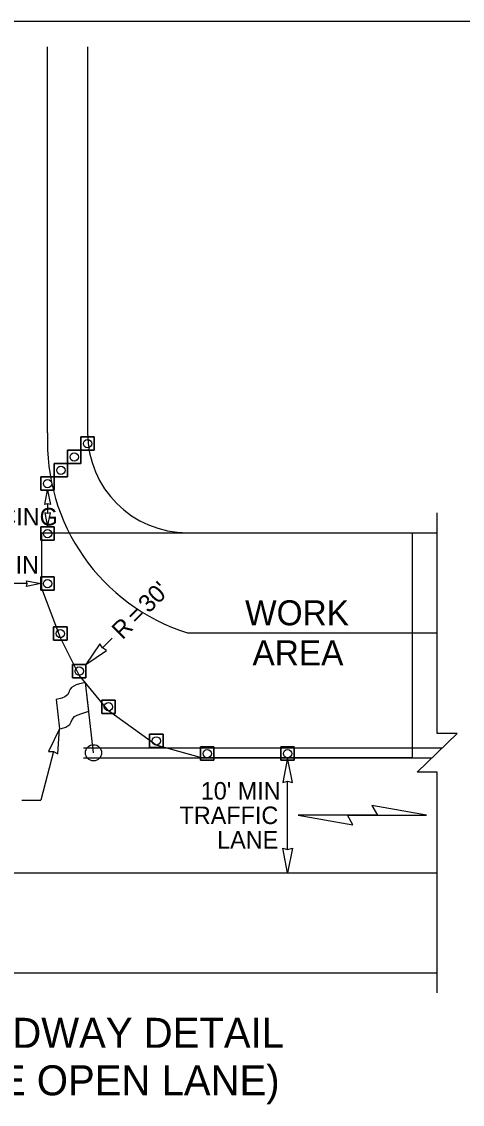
# Model space of a CAD drawing. Extents: x 99999.1 to 100095.7, y 99995 to 100010.7.
# Drawn here: x 100028.611 to 100030.375, y 100001.65 to 100005.98 of the extents above; entities that cross this region are included whole.
import ezdxf

# ---------------------------------------------------------------- set-up
doc = ezdxf.new("R2010")
doc.units = 0
for name, color, linetype in [('RD_ED_ShoulderPavedEdge', 7, 'Continuous'), ('RD_MK_LineDblYellowCenter', 7, 'Continuous'), ('RD_MK_LineEdgeWhite', 7, 'Continuous'), ('SH_DE_DetailHeading2Text', 7, 'Continuous'), ('TR_WZ_FlaggingStation', 7, 'Continuous'), ('TR_WZ_TrafficCone', 7, 'Continuous'), ('TR_WZ_WorkAreaLabel', 7, 'Continuous'), ('TR_WZ_WorkZoneDetails', 7, 'Continuous'), ('TR_WZ_WorkZoneTextCurrent', 7, 'Continuous')]:
    doc.layers.add(name, color=color, linetype=linetype)

msp = doc.modelspace()

# ---------------------------------------------------------------- linework, layer by layer
at = {"layer": 'RD_ED_ShoulderPavedEdge'}
for p, q in [((100029.275, 100003.9359), (100030.275, 100003.9359)), ((100025.475, 100002.1759), (100030.275, 100002.1759))]:
    msp.add_line(p, q, dxfattribs=at)
msp.add_lwpolyline([(100028.875, 100005.8804), (100028.875, 100004.3359)], dxfattribs=at)
msp.add_arc((100029.275, 100004.3359), 0.4, 180, 270, dxfattribs=at)
at = {"layer": 'RD_MK_LineDblYellowCenter'}
for p, q in [((100028.8588, 100003.0759), (100030.2957, 100003.0759)), ((100028.8588, 100003.0359), (100030.2543, 100003.0359))]:
    msp.add_line(p, q, dxfattribs=at)
at = {"layer": 'RD_MK_LineEdgeWhite'}
for p, q in [((100028.715, 100004.3359), (100028.715, 100005.8804)), ((100029.275, 100003.5359), (100030.275, 100003.5359)), ((100025.475, 100002.5759), (100030.275, 100002.5759))]:
    msp.add_line(p, q, dxfattribs=at)
msp.add_arc((100029.5142, 100004.2993), 0.8, 177.3788, 252.6052, dxfattribs=at)
at = {"layer": 'TR_WZ_FlaggingStation'}
for p, q in [((100028.8797, 100003.2228), (100028.8667, 100003.3371)), ((100028.8988, 100003.0559), (100028.8667, 100003.3368)), ((100028.7487, 100003.2693), (100028.762, 100003.1521)), ((100028.8797, 100003.2228), (100028.8797, 100003.2228))]:
    msp.add_line(p, q, dxfattribs=at)
for points in [[(100028.8667, 100003.3371), (100028.8609, 100003.3359), (100028.8431, 100003.3324), (100028.8293, 100003.3283), (100028.8196, 100003.3222), (100028.8111, 100003.3175), (100028.8054, 100003.3106), (100028.8012, 100003.3028), (100028.8006, 100003.2966), (100028.7953, 100003.2874), (100028.7845, 100003.2799), (100028.7721, 100003.2747), (100028.7487, 100003.2693)], [(100028.762, 100003.1521), (100028.7702, 100003.1536), (100028.7879, 100003.1582), (100028.8035, 100003.1687), (100028.81, 100003.1793), (100028.814, 100003.1896), (100028.823, 100003.2005), (100028.834, 100003.2067), (100028.8514, 100003.2138), (100028.8797, 100003.2228)]]:
    msp.add_lwpolyline(points, dxfattribs=at)
msp.add_circle((100028.8988, 100003.0559), 0.0325, dxfattribs=at)
at = {"layer": 'TR_WZ_TrafficCone'}
for points in [[(100028.8483, 100004.3192), (100028.9016, 100004.3192), (100028.9016, 100004.2659), (100028.8483, 100004.2659), (100028.8483, 100004.3192)], [(100028.8483, 100004.2659), (100028.9016, 100004.2659), (100028.9016, 100004.3192), (100028.8483, 100004.3192), (100028.8483, 100004.2659)], [(100028.795, 100004.2659), (100028.8483, 100004.2659), (100028.8483, 100004.2126), (100028.795, 100004.2126), (100028.795, 100004.2659)], [(100028.795, 100004.2126), (100028.8483, 100004.2126), (100028.8483, 100004.2659), (100028.795, 100004.2659), (100028.795, 100004.2126)], [(100028.7416, 100004.2126), (100028.795, 100004.2126), (100028.795, 100004.1592), (100028.7416, 100004.1592), (100028.7416, 100004.2126)], [(100028.7416, 100004.1592), (100028.795, 100004.1592), (100028.795, 100004.2126), (100028.7416, 100004.2126), (100028.7416, 100004.1592)], [(100028.7416, 100004.1592), (100028.6883, 100004.1592), (100028.6883, 100004.1059), (100028.7416, 100004.1059), (100028.7416, 100004.1592)], [(100028.7416, 100004.1059), (100028.6883, 100004.1059), (100028.6883, 100004.1592), (100028.7416, 100004.1592), (100028.7416, 100004.1059)], [(100028.7416, 100003.9592), (100028.6883, 100003.9592), (100028.6883, 100003.9059), (100028.7416, 100003.9059), (100028.7416, 100003.9592)], [(100028.7416, 100003.9059), (100028.6883, 100003.9059), (100028.6883, 100003.9592), (100028.7416, 100003.9592), (100028.7416, 100003.9059)], [(100028.7416, 100003.7592), (100028.6883, 100003.7592), (100028.6883, 100003.7059), (100028.7416, 100003.7059), (100028.7416, 100003.7592)], [(100028.7416, 100003.7059), (100028.6883, 100003.7059), (100028.6883, 100003.7592), (100028.7416, 100003.7592), (100028.7416, 100003.7059)], [(100028.7927, 100003.5592), (100028.7393, 100003.5592), (100028.7393, 100003.5059), (100028.7927, 100003.5059), (100028.7927, 100003.5592)], [(100028.7927, 100003.5059), (100028.7393, 100003.5059), (100028.7393, 100003.5592), (100028.7927, 100003.5592), (100028.7927, 100003.5059)], [(100028.8683, 100003.4093), (100028.815, 100003.4093), (100028.815, 100003.3559), (100028.8683, 100003.3559), (100028.8683, 100003.4093)], [(100028.8683, 100003.3559), (100028.815, 100003.3559), (100028.815, 100003.4093), (100028.8683, 100003.4093), (100028.8683, 100003.3559)], [(100028.9853, 100003.267), (100028.9319, 100003.267), (100028.9319, 100003.2136), (100028.9853, 100003.2136), (100028.9853, 100003.267)], [(100028.9853, 100003.2136), (100028.9319, 100003.2136), (100028.9319, 100003.267), (100028.9853, 100003.267), (100028.9853, 100003.2136)], [(100029.177, 100003.1302), (100029.1236, 100003.1302), (100029.1236, 100003.0768), (100029.177, 100003.0768), (100029.177, 100003.1302)], [(100029.177, 100003.0768), (100029.1236, 100003.0768), (100029.1236, 100003.1302), (100029.177, 100003.1302), (100029.177, 100003.0768)], [(100029.381, 100003.0792), (100029.3276, 100003.0792), (100029.3276, 100003.0259), (100029.381, 100003.0259), (100029.381, 100003.0792)], [(100029.381, 100003.0259), (100029.3276, 100003.0259), (100029.3276, 100003.0792), (100029.381, 100003.0792), (100029.381, 100003.0259)], [(100029.649, 100003.0792), (100029.7024, 100003.0792), (100029.7024, 100003.0259), (100029.649, 100003.0259), (100029.649, 100003.0792)], [(100029.649, 100003.0259), (100029.7024, 100003.0259), (100029.7024, 100003.0792), (100029.649, 100003.0792), (100029.649, 100003.0259)]]:
    msp.add_lwpolyline(points, dxfattribs=at)
for centre in [(100028.875, 100004.2926), (100028.8216, 100004.2392), (100028.7683, 100004.1859), (100028.715, 100004.1326), (100028.715, 100003.9326), (100028.715, 100003.7326), (100028.766, 100003.5326), (100028.8417, 100003.3826), (100028.9586, 100003.2403), (100029.1503, 100003.1035), (100029.3543, 100003.0526), (100029.6757, 100003.0526)]:
    msp.add_circle(centre, 0.0167, dxfattribs=at)
at = {"layer": 'TR_WZ_WorkZoneDetails'}
for p, q in [((100030.5, 100005.9804), (100025.25, 100005.9804)), ((100028.715, 100004.0514), (100028.715, 100004.0137)), ((100028.6338, 100003.7326), (100028.3962, 100003.7326)), ((100028.9346, 100003.4755), (100028.973, 100003.514)), ((100028.7385, 100003.0614), (100028.688, 100002.8668)), ((100029.6756, 100002.6696), (100029.6756, 100002.9422)), ((100028.6118, 100002.8668), (100028.688, 100002.8668)), ((100030.0356, 100002.8059), (100029.7945, 100002.8059)), ((100029.9151, 100002.8059), (100030.1562, 100002.8059))]:
    msp.add_line(p, q, dxfattribs=at)
for points in [[(100028.715, 100004.1059), (100028.7262, 100004.0487), (100028.715, 100004.0514), (100028.7037, 100004.0487)], [(100028.715, 100003.9592), (100028.7262, 100004.0164), (100028.715, 100004.0137), (100028.7038, 100004.0164)], [(100030.175, 100003.9359), (100030.175, 100003.0359), (100029.699, 100003.0359), (100029.6523, 100003.0359), (100029.6523, 100003.0359), (100029.6523, 100003.0359), (100029.331, 100003.0359), (100029.331, 100003.0359), (100029.331, 100003.0359), (100029.1503, 100003.0868), (100028.9586, 100003.2236), (100028.8417, 100003.3659), (100028.766, 100003.5159), (100028.6917, 100003.7126), (100028.6917, 100003.9359)], [(100028.6883, 100003.7326), (100028.6311, 100003.7214), (100028.6338, 100003.7326), (100028.6311, 100003.7438)], [(100028.8683, 100003.4093), (100028.9514, 100003.4652), (100028.9346, 100003.4756), (100028.9242, 100003.4924)], [(100028.762, 100003.1521), (100028.7187, 100003.0618), (100028.7385, 100003.0614), (100028.7561, 100003.0522)], [(100029.6757, 100003.0359), (100029.6564, 100002.9376), (100029.6757, 100002.9422), (100029.695, 100002.9376)], [(100030.2321, 100002.8059), (100030.0133, 100002.8445), (100030.0356, 100002.8059)], [(100029.7185, 100002.8059), (100029.9373, 100002.7673), (100029.9151, 100002.8059)], [(100029.6756, 100002.5759), (100029.6564, 100002.6742), (100029.6756, 100002.6696), (100029.6949, 100002.6742)]]:
    msp.add_lwpolyline(points, close=True, dxfattribs=at)
msp.add_lwpolyline([(100030.275, 100002.0959), (100030.275, 100002.9785), (100030.195, 100002.9785), (100030.355, 100003.1333), (100030.275, 100003.1333), (100030.275, 100004.0159)], dxfattribs=at)

# ---------------------------------------------------------------- texts
at = {"layer": 'SH_DE_DetailHeading2Text'}
for s, p in [('UNSIGNALIZED INTERSECTING ROADWAY DETAIL', (100025.7563, 100001.8759)), ('SAME SIDE AS LANE CLOSURE (SINGLE OPEN LANE)', (100025.524, 100001.6859))]:
    msp.add_text(s, height=0.12, rotation=360, dxfattribs=at).set_placement(p)
at = {"layer": 'TR_WZ_WorkAreaLabel'}
for s, p in [('WORK', (100029.5056, 100003.5659)), ('AREA', (100029.5352, 100003.4059))]:
    msp.add_text(s, height=0.1, dxfattribs=at).set_placement(p)
at = {"layer": 'TR_WZ_WorkZoneTextCurrent'}
for s, p in [('SPACING', (100028.3346, 100003.9654)), ("10' MIN", (100028.3608, 100003.7726)), ("10' MIN", (100029.3283, 100002.8689)), ('TRAFFIC', (100029.2433, 100002.7709)), ('LANE', (100029.3937, 100002.6729))]:
    msp.add_text(s, height=0.07, dxfattribs=at).set_placement(p)
for s, p in [("30'", (100029.1202, 100003.6116)), ('=', (100029.0734, 100003.5648)), ('R', (100029.0142, 100003.5056))]:
    msp.add_text(s, height=0.07, rotation=45, dxfattribs=at).set_placement(p)

doc.saveas('drawing.dxf')
